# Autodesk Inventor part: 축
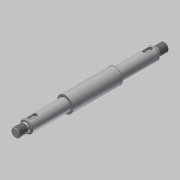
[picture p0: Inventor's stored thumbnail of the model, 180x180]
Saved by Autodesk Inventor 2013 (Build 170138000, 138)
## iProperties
Created: 2018-11
Part Number: 축
Material: 강철, 연강
Document SubType Name: Modeling
Designer: mduedu
Density: 1 g/cm^3
Author: mduedu
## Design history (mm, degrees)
sketch "스케치1"
  geometry: L1 (-35, 0)-(35, 0); L2 (35, 0)-(35, 11); L3 (35, 11)-(-35, 11); L4 (-35, 11)-(-35, 0); L5 (-35, 0)-(-90, 0); L6 (-90, 0)-(-90, 8.5); L7 (-90, 8.5)-(-35, 8.5); L8 (-35, 8.5)-(-35, 0); L9 (-90, 0)-(-105, 0); L10 (-105, 0)-(-105, 6); L11 (-105, 6)-(-90, 6); L12 (-90, 6)-(-90, 0); L13 (0, 0)-(0, 11); L14 (35, 0)-(90, 0); L15 (90, 0)-(90, 8.5); L16 (90, 8.5)-(35, 8.5); L17 (35, 8.5)-(35, 0); L18 (90, 0)-(105, 0); L19 (105, 0)-(105, 6); L20 (105, 6)-(90, 6); L21 (90, 6)-(90, 0); 1 further point
  constraints: 42 end point, 6 parallel, 6 symmetric about line, 3 horizontal, 3 perpendicular, 2 midpoint, 1 coincident
  dimensions: "d0" = 22 diameter of L3 L1; "d2" = 17 diameter of L7 L5; "d3" = 12 diameter of L11 L9; "d4" = 70 distance of L2.end L3.end; "d5" = 55 distance of L6.end L7.end; "d6" = 210 distance between parallel lines of L19 L10
revolve "회전1" sketch "스케치1" stored, may be unused: angle "d7" = 90 deg
fillet "모깎기1" dims "d8" = 0.3
node "작업 평면1"
sketch "스케치2" dims "d11" = 12
  geometry: L1 (15, 2.5)-(22, 2.5); L2 (22, 2.5)-(22, -2.5); L3 (22, -2.5)-(15, -2.5); L4 (15, -2.5)-(15, 2.5); L5 (27.5, 8.5)-(27.5, -8.5) reference; 3 further points
  constraints: 8 end point, 2 midpoint, 2 parallel, 2 vertical alignment, 1 horizontal, 1 horizontal alignment, 1 perpendicular, 4 other
  dimensions: "d9" = 3 dimension on L5; "d10" = 5 distance between parallel lines of L3 L1
extrude "돌출1" cut sketch "스케치2" distance "d12" = 3; taper "d13" = 0 deg
chamfer "모따기1" distance "d14" = 1; stored, may be unused: second distance "d15" = 2, angle "d16" = 45 deg
feature "스레드1" dims "d17" = 12, "d18" = 0
feature "스레드2" dims "d19" = 12, "d20" = 0
chamfer "모따기2" distance "d21" = 1; stored, may be unused: second distance "d22" = 2, angle "d23" = 45 deg
node "솔리드1"
mirror "대칭1"
